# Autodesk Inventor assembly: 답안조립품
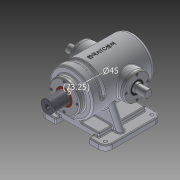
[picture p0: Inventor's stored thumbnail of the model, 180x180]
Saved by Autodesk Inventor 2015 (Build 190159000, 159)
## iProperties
Created: 2015-10
Part Number: 답안조립품
Document SubType Name: Assembly
Designer: youjin17
Mass: 10404.7 g
Surface Area: 4728.45 cm^2
Volume: 2438.34 cm^3
Density: 4.26714 g/cm^3
Author: youjin17
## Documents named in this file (13)
- C:\Users\youjin17\Desktop\351019V1003\답안조립품.iam
- C:\Users\youjin17\Desktop\351019V1003\본체.ipt
- C:\Users\youjin17\Desktop\351019V1003\축 커버.ipt
- C:\Users\youjin17\Desktop\351019V1003\오일실.ipt
- 오일실.ipt
- C:\Users\youjin17\Desktop\351019V1003\M4x0.7.ipt
- C:\Users\youjin17\Desktop\351019V1003\베어링 6205.ipt
- 베어링 6205.ipt
- C:\Users\youjin17\Desktop\351019V1003\편심축.ipt
- C:\Users\youjin17\Desktop\351019V1003\슬라이드 커버.ipt
- C:\Users\youjin17\Desktop\351019V1003\부시.ipt
- C:\Users\youjin17\Desktop\351019V1003\가변 스프링.ipt
- C:\Users\youjin17\Desktop\351019V1003\슬라이드.ipt
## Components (13 placed, 2 different names)
1. 가변 스프링:1
2. M4x0.7:2
3. M4x0.7:6
4. M4x0.7:7
5. M4x0.7:8
6. M4x0.7:9
7. M4x0.7:10
8. M4x0.7:11
9. M4x0.7:12
10. M4x0.7:13
11. M4x0.7:14
12. M4x0.7:15
13. M4x0.7:16
